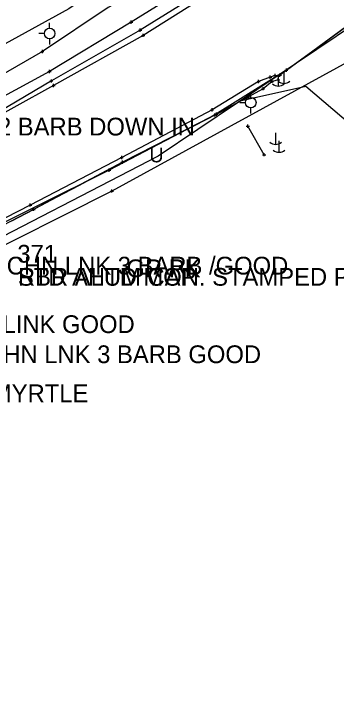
# Model space of a CAD drawing. Extents: x -1 to 1157254, y -1 to 2021979.
# Drawn here: x 1148802.7 to 1148933, y 2018129.3 to 2018412.3 of the extents above; entities that cross this region are included whole.
import ezdxf

# ---------------------------------------------------------------- set-up
doc = ezdxf.new("R2010")
doc.units = 0
for name, color, linetype in [('S_BUILDING_ANNOT', 7, 'Continuous'), ('S_CAL_CORNER_ANNOT', 7, 'Continuous'), ('S_CATCH_BASIN', 7, 'Continuous'), ('S_CONTOUR_ANNOT', 7, 'Continuous'), ('S_CONTOUR_MAJOR', 7, 'Continuous'), ('S_CTL_TABLE', 7, 'Continuous'), ('S_DRIVEWAY_ANNOT', 7, 'Continuous'), ('S_DROP_INLET', 7, 'Continuous'), ('S_DROP_INLET_ANNOT', 7, 'Continuous'), ('S_DTM_PAVEMENT', 7, 'Continuous'), ('S_EDGE_BITUMINOUS_ANNOT', 7, 'Continuous'), ('S_FENCE', 7, 'Continuous'), ('S_GAS_PUMP_ISLAND_ANNOT', 7, 'Continuous'), ('S_GAS_UTILITIES', 7, 'Continuous'), ('S_GATE', 7, 'Continuous'), ('S_GATE_ANNOT', 7, 'Continuous')]:
    doc.layers.add(name, color=color, linetype=linetype)

msp = doc.modelspace()

# ---------------------------------------------------------------- linework, layer by layer
at = {"layer": 'S_BUILDING_ANNOT'}
for p, q in [((1148853.15, 2018405.73), (1148854.42, 2018405.73)), ((1148853.79, 2018405.1), (1148853.78, 2018406.37)), ((1148853.79, 2018405.73), (1148853.79, 2018405.73)), ((1148854.98, 2018402.99), (1148854.98, 2018404.26)), ((1148854.34, 2018403.63), (1148855.62, 2018403.63)), ((1148854.98, 2018403.63), (1148854.98, 2018403.63)), ((1148912.94, 2018388.9), (1148912.94, 2018390.18)), ((1148906.38, 2018386.06), (1148906.38, 2018387.33)), ((1148907.73, 2018387.37), (1148909.01, 2018387.38)), ((1148908.37, 2018386.74), (1148908.37, 2018388.01)), ((1148908.37, 2018387.38), (1148908.37, 2018387.38)), ((1148909.64, 2018387.5), (1148910.91, 2018387.51)), ((1148910.27, 2018386.87), (1148910.27, 2018388.14)), ((1148910.27, 2018387.5), (1148910.27, 2018387.5)), ((1148912.3, 2018389.54), (1148913.57, 2018389.54)), ((1148912.94, 2018389.54), (1148912.94, 2018389.54)), ((1148817.21, 2018385.16), (1148818.48, 2018385.16)), ((1148817.84, 2018384.53), (1148817.84, 2018385.8)), ((1148817.84, 2018385.16), (1148817.84, 2018385.16)), ((1148901.05, 2018384.95), (1148902.32, 2018384.95)), ((1148901.69, 2018384.31), (1148901.68, 2018385.58)), ((1148901.69, 2018384.95), (1148901.69, 2018384.95)), ((1148905.74, 2018386.69), (1148907.02, 2018386.69)), ((1148906.38, 2018386.69), (1148906.38, 2018386.69)), ((1148906.49, 2018384.99), (1148907.76, 2018384.99)), ((1148907.12, 2018384.35), (1148907.12, 2018385.62)), ((1148907.12, 2018384.99), (1148907.12, 2018384.99)), ((1148909.05, 2018385.63), (1148910.32, 2018385.63)), ((1148909.69, 2018385), (1148909.68, 2018386.27)), ((1148909.69, 2018385.63), (1148909.69, 2018385.63)), ((1148818.11, 2018383.31), (1148819.38, 2018383.31)), ((1148818.74, 2018382.67), (1148818.74, 2018383.94)), ((1148818.74, 2018383.31), (1148818.74, 2018383.31)), ((1148902.87, 2018382), (1148904.14, 2018382)), ((1148903.5, 2018381.37), (1148903.5, 2018382.64)), ((1148903.5, 2018382), (1148903.5, 2018382)), ((1148882.23, 2018373.44), (1148883.5, 2018373.44)), ((1148882.87, 2018372.8), (1148882.87, 2018374.07)), ((1148882.87, 2018373.44), (1148882.87, 2018373.44)), ((1148883.38, 2018371.37), (1148884.65, 2018371.37)), ((1148883.97, 2018371.67), (1148885.25, 2018371.67)), ((1148884.02, 2018370.74), (1148884.02, 2018372.01)), ((1148884.02, 2018371.37), (1148884.02, 2018371.37)), ((1148884.61, 2018371.03), (1148884.61, 2018372.31)), ((1148884.61, 2018371.67), (1148884.61, 2018371.67)), ((1148897.31, 2018366.19), (1148897.31, 2018367.46)), ((1148896.68, 2018366.83), (1148897.95, 2018366.83)), ((1148897.31, 2018366.83), (1148897.31, 2018366.83)), ((1148903.98, 2018354.62), (1148903.98, 2018355.89)), ((1148845.67, 2018354.11), (1148846.94, 2018354.12)), ((1148846.31, 2018353.48), (1148846.31, 2018354.75)), ((1148846.31, 2018354.11), (1148846.31, 2018354.11)), ((1148903.34, 2018355.25), (1148904.62, 2018355.25)), ((1148903.98, 2018355.25), (1148903.98, 2018355.25)), ((1148845.92, 2018352.22), (1148847.2, 2018352.22)), ((1148846.56, 2018351.59), (1148846.56, 2018352.86)), ((1148846.56, 2018352.22), (1148846.56, 2018352.22)), ((1148840.63, 2018349), (1148841.9, 2018349)), ((1148841.26, 2018348.36), (1148841.26, 2018349.63)), ((1148841.26, 2018349), (1148841.26, 2018349)), ((1148841.64, 2018340.54), (1148842.92, 2018340.54)), ((1148842.28, 2018339.9), (1148842.28, 2018341.17)), ((1148842.28, 2018340.54), (1148842.28, 2018340.54)), ((1148808.65, 2018334.85), (1148809.93, 2018334.86)), ((1148809.29, 2018334.22), (1148809.29, 2018335.49)), ((1148809.29, 2018334.85), (1148809.29, 2018334.85)), ((1148810.63, 2018332.44), (1148810.63, 2018333.72)), ((1148809.99, 2018333.08), (1148811.26, 2018333.08)), ((1148810.63, 2018333.08), (1148810.63, 2018333.08)), ((1148847.56, 2018309.2), (1148848.83, 2018309.2)), ((1148848.19, 2018308.56), (1148848.19, 2018309.83)), ((1148848.19, 2018309.2), (1148848.19, 2018309.2))]:
    msp.add_line(p, q, dxfattribs=at)
at = {"layer": 'S_CAL_CORNER_ANNOT'}
for points in [[(1148912.94, 2018389.54), (1148938.88, 2018408.55)], [(1148912.94, 2018389.54), (1148884.02, 2018371.37), (1148841.26, 2018349), (1148782.55, 2018319.82), (1148727.8, 2018292.18), (1148687.32, 2018271.68), (1148647.96, 2018251.03), (1148473.78, 2018149.56), (1148431.39, 2018121.98), (1148409.2, 2018106.42), (1148303.97, 2018024.03), (1148255.75, 2017987.09), (1148260.87, 2017979.68), (1148255.56, 2017975.26), (1148250.28, 2017982.33), (1148176.11, 2017926.04), (1148136.14, 2017895.28)]]:
    msp.add_lwpolyline(points, dxfattribs=at)
at = {"layer": 'S_CATCH_BASIN'}
for p, q in [((1148817.13, 2018406.51), (1148817.13, 2018408.76)), ((1148815.04, 2018404.38), (1148812.72, 2018404.38)), ((1148817.21, 2018399.96), (1148817.21, 2018402.29)), ((1148909.63, 2018387.81), (1148909.63, 2018383.08)), ((1148911.92, 2018388.9), (1148911.92, 2018384.18)), ((1148898.52, 2018378.47), (1148898.52, 2018380.72)), ((1148896.42, 2018376.34), (1148894.1, 2018376.34)), ((1148898.59, 2018371.92), (1148898.59, 2018374.25)), ((1148908.55, 2018364.12), (1148908.55, 2018359.39)), ((1148909.95, 2018360.93), (1148909.95, 2018356.21))]:
    msp.add_line(p, q, dxfattribs=at)
for centre in [(1148817.13, 2018404.4), (1148898.52, 2018376.36)]:
    msp.add_circle(centre, 2.13, dxfattribs=at)
for centre in [(1148911.98, 2018387.6), (1148909.69, 2018386.51), (1148908.61, 2018362.82), (1148910.01, 2018359.63)]:
    msp.add_arc(centre, 3.41, 226.3972, 313.6028, dxfattribs=at)
at = {"layer": 'S_CONTOUR_ANNOT'}
msp.add_lwpolyline([(1149931.59, 2019393.98), (1149688.42, 2019230.92), (1149605.65, 2019167.39), (1149471.25, 2019025.78), (1149394.11, 2018934.21), (1149347.84, 2018899.68), (1149226.01, 2018779.47), (1149177.83, 2018729.86), (1148942.89, 2018495.75), (1148824.88, 2018414.4), (1148656.17, 2018321.62), (1148428.99, 2018204.95), (1148398.58, 2018185.48), (1148319.88, 2018123.12), (1148171.01, 2018007.64), (1148133.82, 2017978.13)], dxfattribs=at)
at = {"layer": 'S_CTL_TABLE'}
for p, q in [((1148850.15, 2018408.37), (1148850.14, 2018409.65)), ((1148849.51, 2018409.01), (1148850.78, 2018409.01)), ((1148850.14, 2018409.01), (1148850.14, 2018409.01)), ((1148813.55, 2018397.12), (1148814.83, 2018397.12)), ((1148814.19, 2018396.48), (1148814.19, 2018397.76)), ((1148814.19, 2018397.12), (1148814.19, 2018397.12)), ((1148816.45, 2018388.98), (1148817.72, 2018388.99)), ((1148817.09, 2018388.35), (1148817.08, 2018389.62)), ((1148817.09, 2018388.98), (1148817.09, 2018388.98))]:
    msp.add_line(p, q, dxfattribs=at)
at = {"layer": 'S_DRIVEWAY_ANNOT'}
for points in [[(1148930.72, 2018469.06), (1148929.82, 2018466.88), (1148924.63, 2018459.03), (1148905.96, 2018441.11), (1148885.57, 2018425.64), (1148853.79, 2018405.73), (1148817.84, 2018385.16), (1148785.67, 2018366.18), (1148751.53, 2018348.97), (1148725.91, 2018333.96), (1148694.81, 2018318.17), (1148657.76, 2018297.52), (1148609.03, 2018271.57), (1148572.15, 2018252.4), (1148560.69, 2018247.44)], [(1148931.24, 2018467.87), (1148932.01, 2018465.5), (1148926.13, 2018456.23), (1148907.81, 2018438.7), (1148886.94, 2018423.83), (1148854.98, 2018403.63), (1148818.74, 2018383.31), (1148786.47, 2018365.47), (1148752.66, 2018346.95), (1148727.64, 2018332.49), (1148695.43, 2018316.24), (1148658.96, 2018296.01), (1148609.68, 2018269.54), (1148573.05, 2018250.47), (1148561.71, 2018245.72)], [(1148908.37, 2018387.38), (1148906.38, 2018386.69), (1148901.69, 2018384.95), (1148882.87, 2018373.44), (1148846.31, 2018354.11), (1148809.29, 2018334.85), (1148769.48, 2018314.36), (1148732.4, 2018296.04), (1148710, 2018281.52), (1148703.4, 2018279.32), (1148702.41, 2018277.26)], [(1148909.69, 2018385.63), (1148907.12, 2018384.99), (1148903.5, 2018382), (1148884.61, 2018371.67), (1148846.56, 2018352.22), (1148810.63, 2018333.08), (1148770.15, 2018311.97), (1148733.7, 2018293.45), (1148711.02, 2018280.31), (1148703.82, 2018276.5), (1148702.36, 2018275.6)]]:
    msp.add_lwpolyline(points, dxfattribs=at)
at = {"layer": 'S_DROP_INLET'}
msp.add_lwpolyline([(1149478.88, 2018922.64), (1149385.84, 2018831.36), (1149330.57, 2018775.16), (1149250.6, 2018696.8), (1149231.5, 2018678.75), (1149169.67, 2018614.3), (1149128.45, 2018577.04), (1149075.89, 2018529.44), (1149016.28, 2018476.33), (1148941.34, 2018408.7), (1148861.11, 2018354.7), (1148778.49, 2018311.96), (1148755.86, 2018297.95), (1148577.39, 2018201.52), (1148460.64, 2018136.54), (1148334.57, 2018041.74), (1148195.53, 2017935.77), (1148138.82, 2017892.99)], dxfattribs=at)
at = {"layer": 'S_DROP_INLET_ANNOT'}
msp.add_lwpolyline([(1148942.45, 2018410.87), (1148910.27, 2018387.5)], dxfattribs=at)
at = {"layer": 'S_DTM_PAVEMENT'}
msp.add_lwpolyline([(1148903.98, 2018355.25), (1148897.31, 2018366.83)], dxfattribs=at)
at = {"layer": 'S_EDGE_BITUMINOUS_ANNOT'}
for points in [[(1148926.05, 2018477.74), (1148899.37, 2018448.06), (1148879.25, 2018435.74), (1148840.75, 2018414.9), (1148814.19, 2018397.12), (1148781.62, 2018378.34), (1148757.49, 2018366.59), (1148722.86, 2018348.56), (1148697.99, 2018333.84), (1148668.06, 2018318.01), (1148638.9, 2018301.51), (1148630.09, 2018295.79), (1148605.77, 2018280.64), (1148576.76, 2018263.81), (1148563.59, 2018256.3), (1148552.65, 2018264.54)], [(1148923.02, 2018461.01), (1148903.04, 2018442.9), (1148882.58, 2018429.22), (1148850.14, 2018409.01), (1148817.09, 2018388.98), (1148781.41, 2018369.7), (1148749.49, 2018356.12), (1148727.39, 2018341.81), (1148692.48, 2018321.57), (1148656.83, 2018301.58), (1148607.37, 2018274.07), (1148571.26, 2018254.74)]]:
    msp.add_lwpolyline(points, dxfattribs=at)
at = {"layer": 'S_FENCE'}
msp.add_lwpolyline([(1149562.21, 2019005.4), (1149486.21, 2018927.15), (1149466.96, 2018916.4), (1149448.15, 2018887.45), (1149385.38, 2018826.9), (1149357.5, 2018803.66), (1149334.17, 2018772.97), (1149278.68, 2018714.02), (1149266.21, 2018707.99), (1149250.6, 2018696.75), (1149241.46, 2018677.2), (1149179.13, 2018611.74), (1149130.37, 2018567.15), (1149080.16, 2018520.92), (1149020.19, 2018471.53), (1148946.08, 2018397.31), (1148842.28, 2018340.54), (1148783.26, 2018310.71), (1148755.06, 2018299.13), (1148580.09, 2018196.31), (1148464.77, 2018128.06), (1148357.29, 2018049.22), (1148182.05, 2017918.06), (1148146.03, 2017882.74)], dxfattribs=at)
at = {"layer": 'S_GAS_PUMP_ISLAND_ANNOT'}
msp.add_lwpolyline([(1148801.77, 2018328.46), (1148810.63, 2018333.08), (1148811.29, 2018333.43), (1148820.11, 2018338.13), (1148828.93, 2018342.83), (1148837.74, 2018347.52), (1148846.56, 2018352.22), (1148849.03, 2018353.48), (1148857.92, 2018358.03), (1148866.82, 2018362.58), (1148875.72, 2018367.12), (1148884.61, 2018371.67), (1148885.97, 2018372.41), (1148894.74, 2018377.21), (1148920.82, 2018383.06), (1148946.37, 2018361.31)], dxfattribs=at)

# ---------------------------------------------------------------- texts
at = {"layer": 'S_CONTOUR_MAJOR'}
msp.add_text('U', height=6, dxfattribs=at).set_placement((1148857.48, 2018352.16))
at = {"layer": 'S_GAS_UTILITIES'}
for s, p in [('37', (1148804.06, 2018311.5)), ('371', (1148804.08, 2018311.5)), ('STD AHTD MON. STAMPED PN:37', (1148804.27, 2018302.14)), ('RBR ALUM CAP', (1148804.29, 2018302.14))]:
    msp.add_text(s, height=7.2, dxfattribs=at).set_placement(p)
at = {"layer": 'S_GATE'}
for s, p in [('36"WEB/2 BARB DOWN IN', (1148757.48, 2018363.05)), ("6' CHN LNK 3 BARB /GOOD", (1148789.89, 2018306.68)), ('GR PK', (1148848.19, 2018305.6)), ("3'CHAINLINK GOOD", (1148760.92, 2018282.95)), ("6' CHN LNK 3 BARB GOOD", (1148781.55, 2018270.75))]:
    msp.add_text(s, height=7.2, dxfattribs=at).set_placement(p)
at = {"layer": 'S_GATE_ANNOT'}
msp.add_text('DOUBLE 2" CREPE MYRTLE', height=7.2, dxfattribs=at).set_placement((1148704.19, 2018254.92))

doc.saveas('drawing.dxf')
